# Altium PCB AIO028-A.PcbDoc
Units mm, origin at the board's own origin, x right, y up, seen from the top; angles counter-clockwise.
Board outline 85 x 50 mm, 2 copper layers (TopLayer, BottomLayer); 10 components, 10 nets, 49 pads, 40 vias.
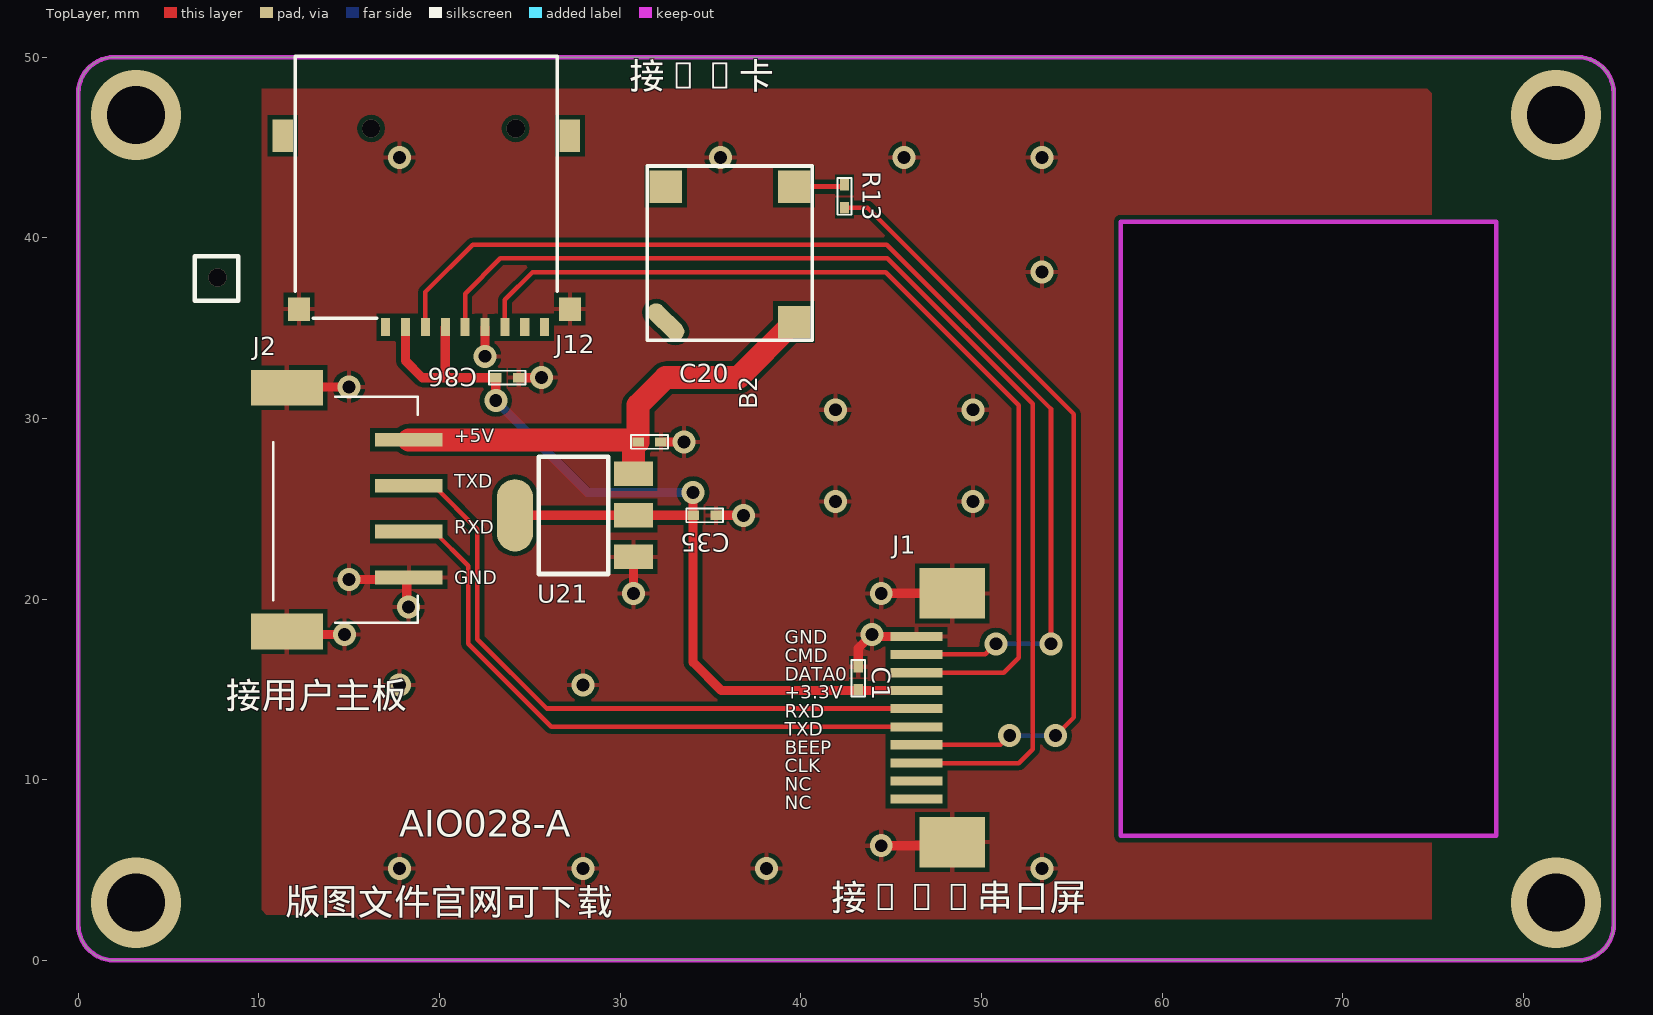
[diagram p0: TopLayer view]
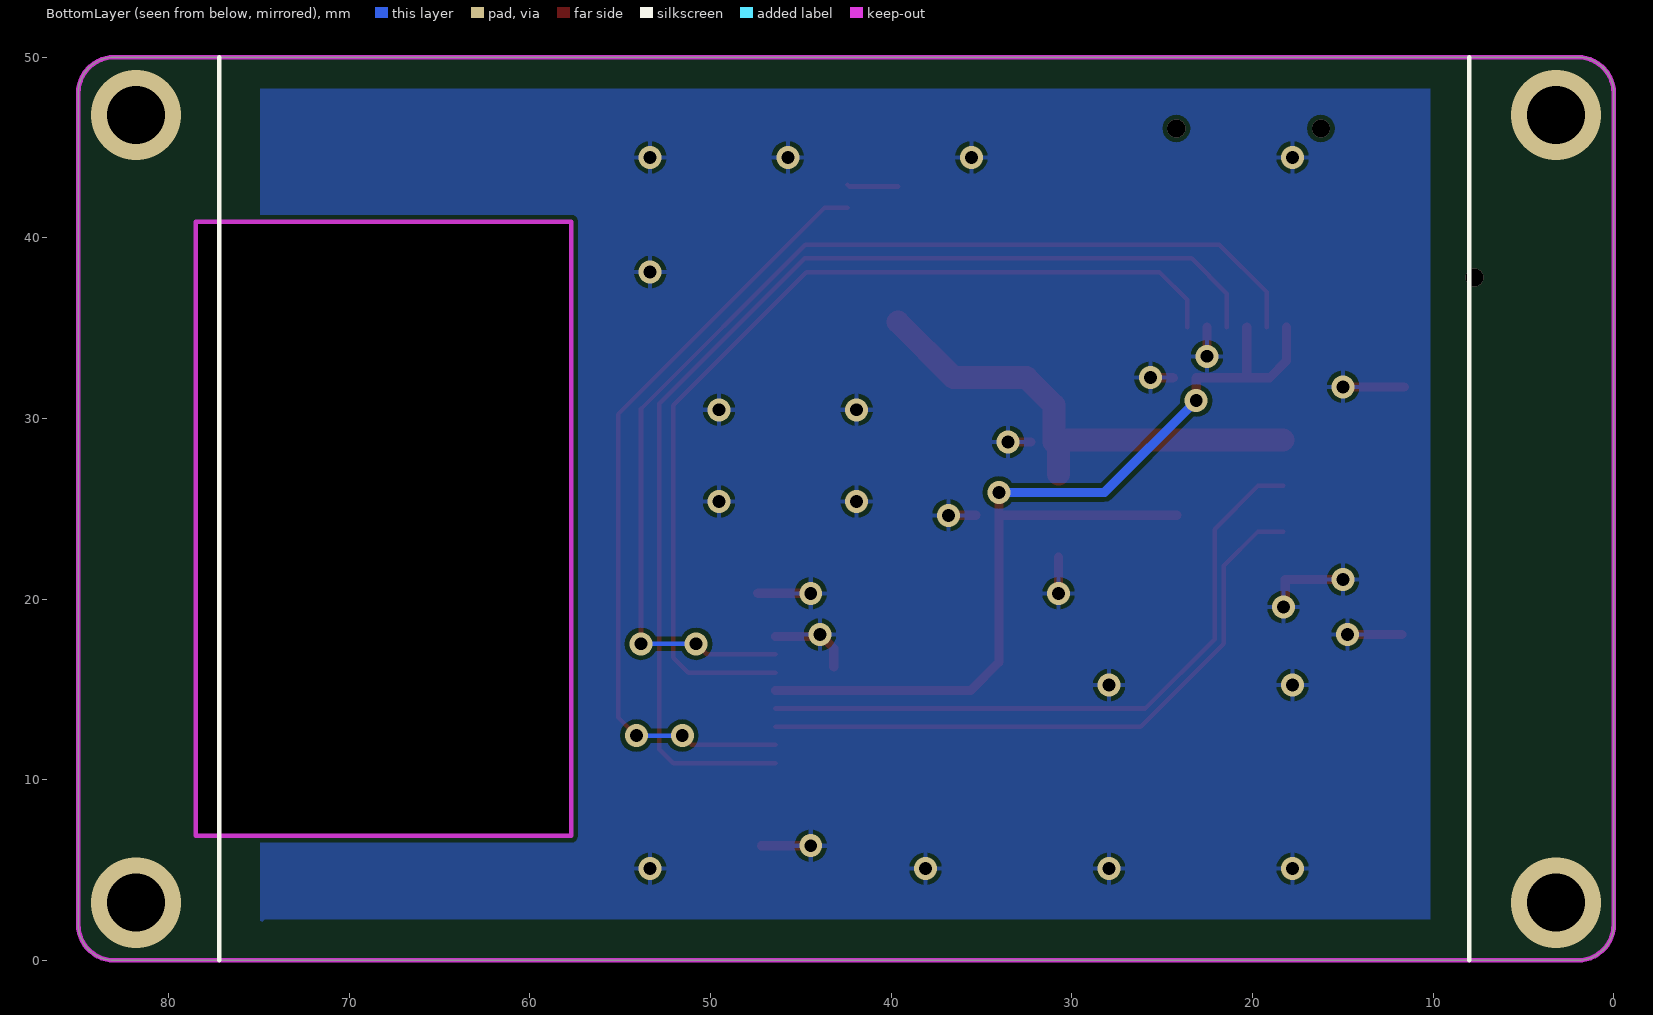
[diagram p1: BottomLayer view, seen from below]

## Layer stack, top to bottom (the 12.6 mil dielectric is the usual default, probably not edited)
TopLayer: signal copper 0.0356
Dielectric: dielectric 0.32, FR-4, Dk 4.8
BottomLayer: signal copper 0.0356

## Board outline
0,2 0,48 cw(c2,48) 2,50 83,50 cw(c83,48) 85,48 85,2 cw(c83,2) 83,0 2,0 cw(c2,2)
cut-out: 57.7,6.9 78.5,6.9 78.5,40.9 57.7,40.9

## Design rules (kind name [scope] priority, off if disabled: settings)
Clearance [All] p1: gap=0.254
FabricationTestPointUsage TestPointUsage [All] p1: valid=0 allowmultiple=FALSE
FabricationTestpoint Testpoint [All] p1: side=3 testpointundercomponent=TRUE minsize=1.016 maxsize=2.54 preferedsize=1.524 minholesize=0.508 maxholesize=1.016 preferedholesize=0.813 testpointgrid=0.025 allowsidetop=TRUE allowsidebottom=TRUE usegrid=TRUE gridtolerance=0
HoleSize [All] p1: absolutevalues=TRUE maxlimit=7.62 minlimit=0.025 maxpercent=80.000 minpercent=20.000
PolygonConnect [All] p1: connectstyle=Relief reliefconductorwidth=0.254 reliefentries=4 polygonreliefangle="90 Angle"
RoutingVias [All] p1: holewidth=0.711 width=1.27 viastyle="Through Hole" minholewidth=0.711 minwidth=1.27 maxholewidth=0.711 maxwidth=1.27
SilkToSilkClearance [All] p1: silktosilkclearance=0
SilkscreenOverComponentPads [All] p1: minsilkscreentomaskgap=0
SolderMaskExpansion [All] p1: expansion=0.102
Width [All] p1: maxlimit=1.27 minlimit=0.152 preferedwidth=0.508 minimp=50.000000 maximp=50.000000 favimp=50.000000
23 further rules are at their usual default settings.

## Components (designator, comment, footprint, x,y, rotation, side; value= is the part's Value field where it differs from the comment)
B2 "KLJ-8530" BEEP 39.624,35.338 r90 top
C1 "4.7uF/6.3V" 0402A 43.18,14.986 r90 top
C20 "4.7uF/6.3V" 0402A 30.988,28.702 r0 top
C35 "4.7uF/6.3V" 0402A 34.036,24.638 r0 top
C86 "4.7uF/6.3V" 0402A 23.114,32.258 r0 top
J1 "FPC1.0-10下接" FPC1.0-10下接 46.4,8.94 r90 top locked
J2 "2.0-4" FPC2.54-4 18.3,21.2 r270 top locked
J12 "TF卡" TF卡 17.018,35.052 r180 top locked
R13 "62R" 0402A 42.418,42.926 r270 top
U21 "AMS1117-3.3" AMS1117-3.3 30.734,24.638 r90 top

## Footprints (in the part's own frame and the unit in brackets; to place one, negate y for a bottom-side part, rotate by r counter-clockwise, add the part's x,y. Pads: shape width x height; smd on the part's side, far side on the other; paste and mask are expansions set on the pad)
0402A [mil]
  rect 25x20 smd: 1(0,0) 2(50,0)
  silkscreen extent -15,-15 65,15
AMS1117-3.3 [mm]
  rect 1.35x2.15 smd: 1(-2.3,0) 2(0,0) 3(2.3,0)
  oval 4x2 smd: 4(0,6.56)
  silkscreen extent -3.25,1.4 3.25,5.25
BEEP [mm]
  rect 1.8x1.8 smd: 1(0,0) 2(7.5,0) 3(7.5,7.1)
  oval 2.5x1 smd rot 45: 4(0,7.1)
  silkscreen extent -1.02,-1.02 8.64,8.13
FPC1.0-10下接 [mil]
  rect 20x114 smd: 1(0,0) 2(39,0) 3(78,0) 4(118,0) 5(157,0) 6(197,0) 7(236,0) 8(275,0) 9(315,0) 10(354,0)
  rect 110x142 smd: 11(-94,-78) 12(448,-78)
FPC2.54-4 [mil]
  rect 30x147 smd: 1(0,0) 2(-100,0) 3(-200,0) 4(-300,0)
  rect 78x157 smd: 5(118.11,-265.75) 6(-413.39,-265.75)
  silkscreen extent -394,-295 99,20
TF卡 [mm]
  rect 0.5x1 smd: 1(0,0) 2(-1.1,0) 3(-2.2,0) 4(-3.3,0) 5(-4.4,0) 6(-5.5,0) 7(-6.6,0) 8(-7.7,0) 9(-8.8,0)
  rect 1.2x1.3 smd: 10(4.8,-1) 11(-10.2,-1)
  rect 1.143x1.778 smd: 12(5.7,-10.6) 13(-10.2,-10.6)
  silkscreen extent -9.5,-15 5,-0.5

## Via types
v1: diameter 1.27, hole 0.711, TopLayer to BottomLayer, 33 vias
v2: diameter 5, hole 3.2, TopLayer to BottomLayer, 4 vias
v3: diameter 1, hole 1, TopLayer to BottomLayer, 3 vias

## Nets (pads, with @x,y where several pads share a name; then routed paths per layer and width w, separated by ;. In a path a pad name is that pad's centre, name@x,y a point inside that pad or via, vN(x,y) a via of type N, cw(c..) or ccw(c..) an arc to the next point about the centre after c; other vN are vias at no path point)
3.3V: C1.1 C35.1 C86.1 J1.7 J12.2 J12.4 U21.2 U21.4 | length 56.6
  TopLayer w0.508: J12.2 18.118,33.19 19.05,32.258 C86.1 v1(23.114,30.988) ; 20.318,32.26 J12.4 ; U21.4 U21.2 C35.1 ; v1(34.036,25.908) C35.1 ; J1.7 35.612,14.934 34.036,16.51 C35.1
  BottomLayer w0.508: v1(23.114,30.988) 28.194,25.908 v1(34.036,25.908)
5V: B2.1 C20.1 J2.4 U21.3 | length 27.1
  TopLayer w1.27: J2.4 30.87,28.82 30.734,28.684 U21.3 ; C20.1 30.988,30.734 32.512,32.258 36.544,32.258 B2.1
BEEP: J1.4 R13.2 | length 44.3
  TopLayer w0.254: R13.2 43.688,41.656 55.118,30.226 55.118,13.462 v1@54.356,12.7 ; J1.4 51.053,11.937 v1(51.562,12.446) v1@51.054,12.446 ; v1(54.102,12.446) v1@54.356,12.7 ; v1@54.356,12.446 v1@54.356,12.7
  BottomLayer w0.254: v1(51.562,12.446) v1(54.102,12.446)
CLK: J1.3 J12.5 | length 63.3
  TopLayer w0.254: J12.5 21.418,36.912 23.368,38.862 44.791,38.862 52.832,30.821 52.832,11.684 52.069,10.921 J1.3
CMD: J1.9 J12.3 | length 62.1
  TopLayer w0.254: J12.3 19.218,36.998 21.844,39.624 44.748,39.624 53.848,30.524 v1(53.848,17.526) ; J1.9 50.215,16.941 v1(50.8,17.526)
  BottomLayer w0.254: v1(50.8,17.526) v1(53.848,17.526)
DAT0: J1.8 J12.7 | length 53.6
  TopLayer w0.254: J12.7 23.618,36.572 25.146,38.1 44.704,38.1 52.07,30.734 52.07,16.764 51.231,15.925 J1.8
GND: C1.2 C20.2 C35.2 C86.2 J1.10 J1.11 J1.12 J2.1 J2.5 J2.6 J12.6 J12.10 J12.11 U21.1 | length 29
  TopLayer w0.508: J2.6@11.6,31.75 v1(14.986,31.75) ; J2.5@11.716,18.034 v1(14.732,18.034) ; v1(14.986,21.082) 18.182,21.082 v1@18.182,19.664 ; v1(22.518,33.44) J12.6 ; C86.2 v1(25.654,32.258) ; v1(30.734,20.32) U21.1 ; C20.2 v1(33.528,28.702) ; C35.2 v1(36.83,24.638) ; C1.2 43.18,17.272 v1(43.942,18.034) 44.044,17.932 J1.10 ; v1(44.45,6.35) J1.11@47.179,6.35 ; v1(44.45,20.32) J1.12@47.38,20.32
  other v1: 17.78,5.08 27.94,5.08 38.1,5.08 53.34,5.08 17.78,15.24 27.94,15.24 18.288,19.558 41.91,25.4 49.53,25.4 41.91,30.48 49.53,30.48 53.34,38.1 17.78,44.45 35.56,44.45 45.72,44.45 53.34,44.45
NetB2_2: B2.2 R13.1 | length 2.8
  TopLayer w0.254: B2.2 42.33,42.838 R13.1
RXD: J1.5 J2.2 | length 35.1
  TopLayer w0.254: J2.2 19.694,23.74 21.59,21.844 21.59,17.526 26.188,12.928 J1.5
TXD: J1.6 J2.3 | length 36.8
  TopLayer w0.254: J2.3 19.694,26.28 22.098,23.876 22.098,17.78 25.934,13.944 J1.6
pads on no net: B2.3 B2.4 J1.1 J1.2 J12.1 J12.8 J12.9 J12.12 J12.13
copper on no net:
  other v2: 3.2,3.2 81.8,3.2 3.2,46.8 81.8,46.8
  other v3: 7.7,37.8 16.218,46.052 24.218,46.052

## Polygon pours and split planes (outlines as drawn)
GND on TopLayer "TopLayer-No Net" (solid, remove dead copper, pour order 2): 10.16,48.26 74.676,48.26 74.93,48.006 74.93,2.286 15.494,2.286 15.24,2.54 13.97,2.54 10.414,2.54 10.16,2.794
GND on BottomLayer "TopLayer-No Net" (solid, remove dead copper, pour order 4): 10.16,48.26 74.93,48.26 74.93,2.032 74.676,2.286 10.16,2.286

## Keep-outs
KeepOutLayer:
  lines w0.254: 0,2 ccw(c2,2) 2,0 83,0 ccw(c83,2) 85,2 85,48 ccw(c83,48) 83,50 2,50 ccw(c2,48) 0,48 0,2 ; 57.7,6.9 57.7,40.9 78.5,40.9 78.5,6.9 57.7,6.9

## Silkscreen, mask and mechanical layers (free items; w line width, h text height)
TopOverlay:
  lines w0.254: 6.452,36.525 8.865,36.525 8.865,38.989 6.452,38.989 6.452,36.525
  text "接TF卡" at 30.48,47.752 h2.54
  text "+5V" at 20.828,28.448 h1.27
  text "TXD" at 20.828,25.908 h1.27
  text "RXD" at 20.828,23.368 h1.27
  text "GND" at 20.828,20.574 h1.27
  text "GND" at 39.116,17.272 h1.27
  text "CMD" at 39.116,16.256 h1.27
  text "DATA0" at 39.116,15.24 h1.27
  text "+3.3V" at 39.116,14.229 h1.27
  text "接用户主板" at 8.128,13.462 h2.54
  text "RXD" at 39.117,13.197 h1.27
  text "TXD" at 39.116,12.181 h1.27
  text "BEEP" at 39.116,11.165 h1.27
  text "CLK" at 39.116,10.16 h1.27
  text "NC" at 39.117,9.144 h1.27
  text "NC" at 39.117,8.128 h1.27
  text "AIO028-A" at 17.78,6.35 h2.54
  text "接AIO串口屏" at 41.656,2.286 h2.54
  text "版图文件官网可下载" at 11.43,2.032 h2.54
BottomOverlay:
  lines w0.254: 8,0 8,50 ; 77.2,0 77.2,50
